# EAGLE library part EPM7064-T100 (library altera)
EPM7064 MAX 7000 family
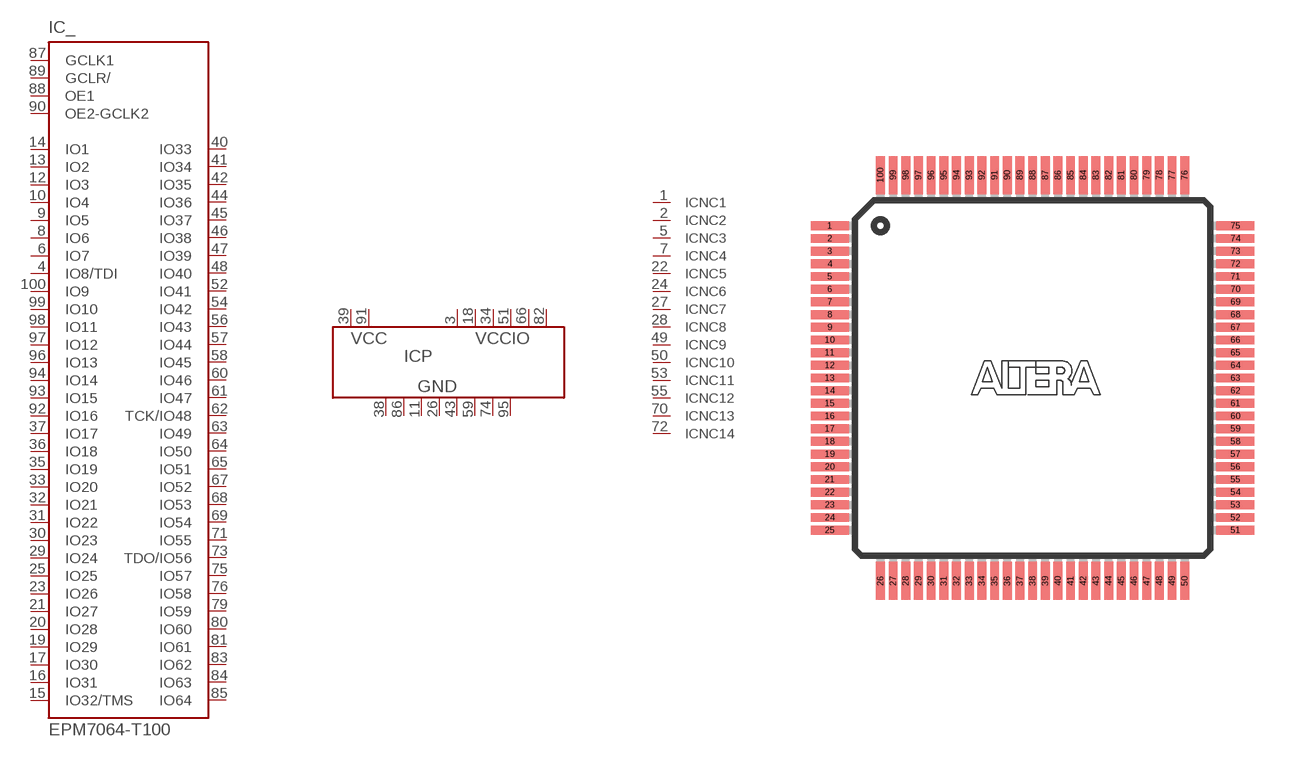
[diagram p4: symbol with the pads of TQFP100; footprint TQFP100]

Designator prefix IC; gates _=EPM7064S P=PWR8-2-6 NC1=NC NC2=NC NC3=NC NC4=NC NC5=NC NC6=NC NC7=NC NC8=NC NC9=NC NC10=NC NC11=NC NC12=NC NC13=NC NC14=NC NC15=NC NC16=NC

## EPM7064-T100 (MPN: EPM7064STI100-7N; OC_FARNELL: 1549426; OC_NEWARK: 51R9650)  [TQFP100]
1  NC1:NC  nc
2  NC2:NC  nc
3  P:VCCIO  pwr
4  _:IO8/TDI
5  NC3:NC  nc
6  _:IO7
7  NC4:NC  nc
8  _:IO6
9  _:IO5
10  _:IO4
11  P:GND  pwr
12  _:IO3
13  _:IO2
14  _:IO1
15  _:IO32/TMS
16  _:IO31
17  _:IO30
18  P:VCCIO  pwr
19  _:IO29
20  _:IO28
21  _:IO27
22  NC5:NC  nc
23  _:IO26
24  NC6:NC  nc
25  _:IO25
26  P:GND  pwr
27  NC7:NC  nc
28  NC8:NC  nc
29  _:IO24
30  _:IO23
31  _:IO22
32  _:IO21
33  _:IO20
34  P:VCCIO  pwr
35  _:IO19
36  _:IO18
37  _:IO17
38  P:GND  pwr
39  P:VCC  pwr
40  _:IO33
41  _:IO34
42  _:IO35
43  P:GND  pwr
44  _:IO36
45  _:IO37
46  _:IO38
47  _:IO39
48  _:IO40
49  NC9:NC  nc
50  NC10:NC  nc
51  P:VCCIO  pwr
52  _:IO41
53  NC11:NC  nc
54  _:IO42
55  NC12:NC  nc
56  _:IO43
57  _:IO44
58  _:IO45
59  P:GND  pwr
60  _:IO46
61  _:IO47
62  _:TCK/IO48
63  _:IO49
64  _:IO50
65  _:IO51
66  P:VCCIO  pwr
67  _:IO52
68  _:IO53
69  _:IO54
70  NC13:NC  nc
71  _:IO55
72  NC14:NC  nc
73  _:TDO/IO56
74  P:GND  pwr
75  _:IO57
76  _:IO58
77  NC15:NC  nc
78  NC16:NC  nc
79  _:IO59
80  _:IO60
81  _:IO61
82  P:VCCIO  pwr
83  _:IO62
84  _:IO63
85  _:IO64
86  P:GND  pwr
87  _:GCLK1  in
88  _:OE1  in
89  _:GCLR/  in
90  _:OE2-GCLK2  in
91  P:VCC  pwr
92  _:IO16
93  _:IO15
94  _:IO14
95  P:GND  pwr
96  _:IO13
97  _:IO12
98  _:IO11
99  _:IO10
100  _:IO9

## Footprint TQFP100 (pad centres in mm)
Plastic Thin Quad Flat Pack
smd 1.5 x 0.35: 1 -8,6; 2 -8,5.5; 3 -8,5; 4 -8,4.5; 5 -8,4; 6 -8,3.5; 7 -8,3; 8 -8,2.5; 9 -8,2; 10 -8,1.5; 11 -8,1; 12 -8,0.5; 13 -8,0; 14 -8,-0.5; 15 -8,-1; 16 -8,-1.5; 17 -8,-2; 18 -8,-2.5; 19 -8,-3; 20 -8,-3.5; 21 -8,-4; 22 -8,-4.5; 23 -8,-5; 24 -8,-5.5; 25 -8,-6; 51 8,-6; 52 8,-5.5; 53 8,-5; 54 8,-4.5; 55 8,-4; 56 8,-3.5; 57 8,-3; 58 8,-2.5; 59 8,-2; 60 8,-1.5; 61 8,-1; 62 8,-0.5; 63 8,0; 64 8,0.5; 65 8,1; 66 8,1.5; 67 8,2; 68 8,2.5; 69 8,3; 70 8,3.5; 71 8,4; 72 8,4.5; 73 8,5; 74 8,5.5; 75 8,6
smd 0.35 x 1.5: 26 -6,-8; 27 -5.5,-8; 28 -5,-8; 29 -4.5,-8; 30 -4,-8; 31 -3.5,-8; 32 -3,-8; 33 -2.5,-8; 34 -2,-8; 35 -1.5,-8; 36 -1,-8; 37 -0.5,-8; 38 0,-8; 39 0.5,-8; 40 1,-8; 41 1.5,-8; 42 2,-8; 43 2.5,-8; 44 3,-8; 45 3.5,-8; 46 4,-8; 47 4.5,-8; 48 5,-8; 49 5.5,-8; 50 6,-8; 76 6,8; 77 5.5,8; 78 5,8; 79 4.5,8; 80 4,8; 81 3.5,8; 82 3,8; 83 2.5,8; 84 2,8; 85 1.5,8; 86 1,8; 87 0.5,8; 88 0,8; 89 -0.5,8; 90 -1,8; 91 -1.5,8; 92 -2,8; 93 -2.5,8; 94 -3,8; 95 -3.5,8; 96 -4,8; 97 -4.5,8; 98 -5,8; 99 -5.5,8; 100 -6,8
